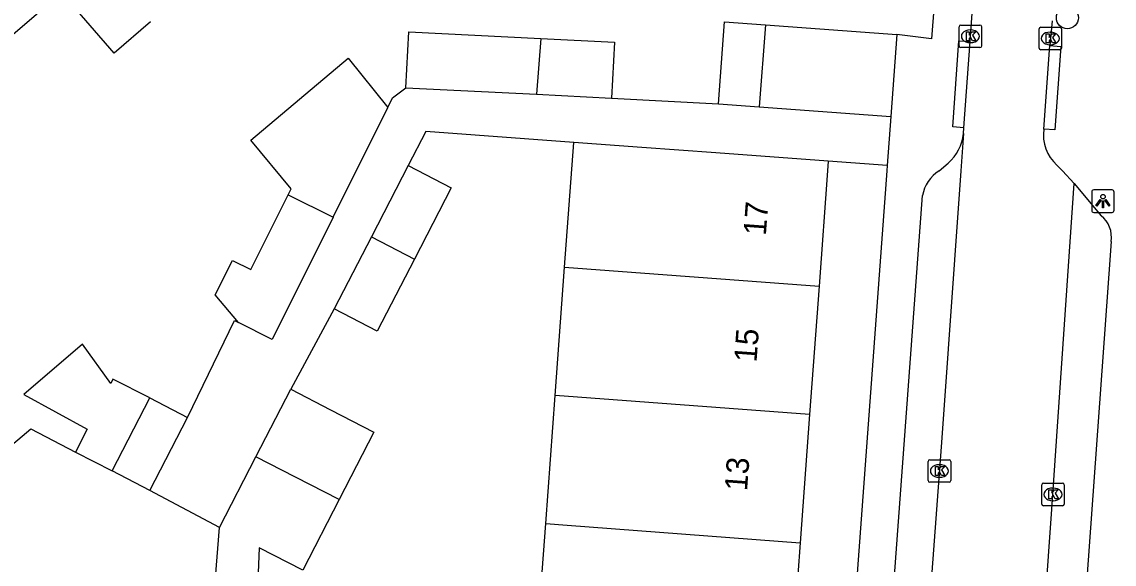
# Model space of a CAD drawing. Extents: x 160304 to 160954, y 383686 to 384161.
# Drawn here: x 160475.81 to 160524.27, y 383982.56 to 384006.62 of the extents above; entities that cross this region are included whole.
import ezdxf

# ---------------------------------------------------------------- set-up
doc = ezdxf.new("R2010")
doc.units = 0
for name, color, linetype in [('IMGEO_Boom', 7, 'Continuous'), ('IMGEO_Kolk', 7, 'Continuous'), ('IMGEO_Lichtpunt', 7, 'Continuous'), ('IMGEO_Muur', 7, 'Continuous'), ('IMGEO_Pand', 7, 'Continuous'), ('IMGEO_Pand_nummerreeks', 7, 'Continuous'), ('IMGEO_Rijbaan_lokaal_open', 7, 'Continuous'), ('IMGEO_Voetpad_open', 7, 'Continuous')]:
    doc.layers.add(name, color=color, linetype=linetype)

msp = doc.modelspace()

# ---------------------------------------------------------------- linework, layer by layer
at = {"layer": 'IMGEO_Boom'}
msp.add_circle((160522.195, 384006.799), 0.489, dxfattribs=at)
at = {"layer": 'IMGEO_Kolk'}
for p, q in [((160517.392, 384005.549), (160517.392, 384006.401)), ((160517.467, 384006.475), (160518.319, 384006.475)), ((160517.88, 384006.255), (160517.905, 384006.255)), ((160518.393, 384006.401), (160518.393, 384005.549)), ((160520.937, 384005.453), (160520.937, 384006.305)), ((160521.012, 384006.379), (160521.864, 384006.379)), ((160521.938, 384006.305), (160521.938, 384005.453)), ((160521.425, 384006.159), (160521.45, 384006.159)), ((160518.319, 384005.475), (160517.467, 384005.475)), ((160517.903, 384005.695), (160517.878, 384005.695)), ((160521.864, 384005.379), (160521.012, 384005.379)), ((160521.448, 384005.599), (160521.423, 384005.599)), ((160516.017, 383986.267), (160516.017, 383987.119)), ((160516.092, 383987.193), (160516.944, 383987.193)), ((160516.505, 383986.973), (160516.53, 383986.973)), ((160517.018, 383987.119), (160517.018, 383986.267)), ((160516.528, 383986.413), (160516.503, 383986.413)), ((160516.944, 383986.193), (160516.092, 383986.193)), ((160521.055, 383985.227), (160521.055, 383986.079)), ((160521.13, 383986.153), (160521.982, 383986.153)), ((160521.543, 383985.933), (160521.568, 383985.933)), ((160522.056, 383986.079), (160522.056, 383985.227)), ((160521.566, 383985.373), (160521.541, 383985.373)), ((160521.982, 383985.153), (160521.13, 383985.153))]:
    msp.add_line(p, q, dxfattribs=at)
for points in [[(160517.392, 384005.549), (160517.392, 384006.401)], [(160517.467, 384006.475), (160518.319, 384006.475)], [(160518.393, 384006.401), (160518.393, 384005.549)], [(160520.937, 384005.453), (160520.937, 384006.305)], [(160521.012, 384006.379), (160521.864, 384006.379)], [(160521.938, 384006.305), (160521.938, 384005.453)], [(160517.713, 384006.175), (160517.836, 384006.175), (160517.836, 384006.024), (160517.966, 384006.175), (160518.13, 384006.175), (160517.984, 384006.024), (160518.137, 384005.775), (160517.985, 384005.775), (160517.9, 384005.939), (160517.836, 384005.872), (160517.836, 384005.775), (160517.713, 384005.775), (160517.713, 384006.175)], [(160521.258, 384006.079), (160521.381, 384006.079), (160521.381, 384005.928), (160521.511, 384006.079), (160521.675, 384006.079), (160521.529, 384005.928), (160521.682, 384005.679), (160521.53, 384005.679), (160521.445, 384005.843), (160521.381, 384005.776), (160521.381, 384005.679), (160521.258, 384005.679), (160521.258, 384006.079)], [(160518.319, 384005.475), (160517.467, 384005.475)], [(160521.864, 384005.379), (160521.012, 384005.379)], [(160516.017, 383986.267), (160516.017, 383987.119)], [(160516.092, 383987.193), (160516.944, 383987.193)], [(160516.338, 383986.893), (160516.461, 383986.893), (160516.461, 383986.742), (160516.591, 383986.893), (160516.755, 383986.893), (160516.609, 383986.742), (160516.762, 383986.493), (160516.61, 383986.493), (160516.525, 383986.657), (160516.461, 383986.59), (160516.461, 383986.493), (160516.338, 383986.493), (160516.338, 383986.893)], [(160517.018, 383987.119), (160517.018, 383986.267)], [(160516.944, 383986.193), (160516.092, 383986.193)], [(160521.055, 383985.227), (160521.055, 383986.079)], [(160521.13, 383986.153), (160521.982, 383986.153)], [(160522.056, 383986.079), (160522.056, 383985.227)], [(160521.376, 383985.853), (160521.499, 383985.853), (160521.499, 383985.702), (160521.629, 383985.853), (160521.793, 383985.853), (160521.647, 383985.702), (160521.8, 383985.453), (160521.648, 383985.453), (160521.563, 383985.617), (160521.499, 383985.55), (160521.499, 383985.453), (160521.376, 383985.453), (160521.376, 383985.853)], [(160521.982, 383985.153), (160521.13, 383985.153)]]:
    msp.add_lwpolyline(points, dxfattribs=at)
for centre, start, end in [((160517.469, 384006.399), 91.552, 178.448), ((160517.469, 384006.399), 91.552, 178.448), ((160518.317, 384006.399), 1.552, 88.448), ((160518.317, 384006.399), 1.552, 88.448), ((160521.014, 384006.303), 91.552, 178.448), ((160521.014, 384006.303), 91.552, 178.448), ((160521.862, 384006.303), 1.552, 88.448), ((160521.862, 384006.303), 1.552, 88.448), ((160517.469, 384005.551), 181.552, 268.448), ((160517.469, 384005.551), 181.552, 268.448), ((160518.317, 384005.551), 271.552, 358.448), ((160518.317, 384005.551), 271.552, 358.448), ((160521.014, 384005.455), 181.552, 268.448), ((160521.014, 384005.455), 181.552, 268.448), ((160521.862, 384005.455), 271.552, 358.448), ((160521.862, 384005.455), 271.552, 358.448), ((160516.094, 383987.117), 91.552, 178.448), ((160516.094, 383987.117), 91.552, 178.448), ((160516.942, 383987.117), 1.552, 88.448), ((160516.942, 383987.117), 1.552, 88.448), ((160516.094, 383986.269), 181.552, 268.448), ((160516.094, 383986.269), 181.552, 268.448), ((160516.942, 383986.269), 271.552, 358.448), ((160516.942, 383986.269), 271.552, 358.448), ((160521.132, 383986.077), 91.552, 178.448), ((160521.132, 383986.077), 91.552, 178.448), ((160521.98, 383986.077), 1.552, 88.448), ((160521.98, 383986.077), 1.552, 88.448), ((160521.132, 383985.229), 181.552, 268.448), ((160521.132, 383985.229), 181.552, 268.448), ((160521.98, 383985.229), 271.552, 358.448), ((160521.98, 383985.229), 271.552, 358.448)]:
    msp.add_arc(centre, 0.0765, start, end, dxfattribs=at)
for centre, major_axis, ratio, start_param, end_param in [((160517.879, 384005.975), (-0.387, 0.002), 0.722429, 4.712389, 7.853982), ((160517.904, 384005.975), (-0.39, 0.002), 0.717154, 1.570796, 4.712389), ((160521.424, 384005.879), (-0.387, 0.002), 0.722429, 4.712389, 7.853982), ((160521.449, 384005.879), (-0.39, 0.002), 0.717154, 1.570796, 4.712389), ((160516.504, 383986.693), (-0.387, 0.002), 0.722429, 4.712389, 7.853982), ((160516.529, 383986.693), (-0.39, 0.002), 0.717154, 1.570796, 4.712389), ((160521.542, 383985.653), (-0.387, 0.002), 0.722429, 4.712389, 7.853982), ((160521.567, 383985.653), (-0.39, 0.002), 0.717154, 1.570796, 4.712389)]:
    msp.add_ellipse(centre, major_axis=major_axis, ratio=ratio, start_param=start_param, end_param=end_param, dxfattribs=at)
at = {"layer": 'IMGEO_Lichtpunt'}
for p, q in [((160523.274, 383999.065), (160523.274, 383998.258)), ((160523.274, 383999.065), (160523.274, 383998.258)), ((160524.176, 383999.16), (160523.368, 383999.16)), ((160524.176, 383999.16), (160523.368, 383999.16)), ((160524.27, 383998.258), (160524.27, 383999.065)), ((160524.27, 383998.258), (160524.27, 383999.065)), ((160523.368, 383998.164), (160524.176, 383998.164)), ((160523.368, 383998.164), (160524.176, 383998.164))]:
    msp.add_line(p, q, dxfattribs=at)
for points in [[(160523.648, 383998.729), (160523.687, 383998.701), (160523.499, 383998.439), (160523.461, 383998.466), (160523.648, 383998.729)], [(160523.75, 383998.681), (160523.797, 383998.681), (160523.797, 383998.359), (160523.75, 383998.359), (160523.75, 383998.681)], [(160523.86, 383998.701), (160523.898, 383998.728), (160524.085, 383998.466), (160524.046, 383998.438), (160523.86, 383998.701)]]:
    msp.add_lwpolyline(points, dxfattribs=at)
msp.add_circle((160523.773, 383998.863), 0.0994, dxfattribs=at)
for centre, start, end in [((160523.368, 383999.065), 90, 180), ((160523.368, 383999.065), 90, 180), ((160524.176, 383999.065), 0, 90), ((160524.176, 383999.065), 0, 90), ((160523.368, 383998.258), 180, 270), ((160523.368, 383998.258), 180, 270), ((160524.176, 383998.258), 270, 0), ((160524.176, 383998.258), 270, 360)]:
    msp.add_arc(centre, 0.0946, start, end, dxfattribs=at)
at = {"layer": 'IMGEO_Muur'}
msp.add_lwpolyline([(160516.865, 384014.823), (160516.165, 384005.868), (160514.632, 384006.049)], dxfattribs=at)
at = {"layer": 'IMGEO_Pand'}
for points in [[(160481.518, 384006.62), (160479.908, 384005.23), (160477.59, 384007.917), (160474.915, 384005.61)], [(160506.718, 384002.979), (160506.985, 384006.611), (160508.803, 384006.477)], [(160508.803, 384006.477), (160508.529, 384002.846)], [(160508.803, 384006.477), (160514.632, 384006.049)], [(160492.852, 384003.691), (160492.976, 384006.17), (160498.838, 384005.876)], [(160498.838, 384005.876), (160498.645, 384003.401)], [(160498.838, 384005.876), (160502.101, 384005.712), (160501.977, 384003.234)], [(160514.632, 384006.049), (160514.365, 384002.417)], [(160487.627, 383998.942), (160487.762, 383999.213), (160485.973, 384001.37), (160490.297, 384005.007), (160492.045, 384002.818)], [(160492.852, 384003.691), (160498.645, 384003.401)], [(160498.645, 384003.401), (160501.977, 384003.234)], [(160489.621, 383997.952), (160492.045, 384002.818)], [(160506.718, 384002.979), (160508.529, 384002.846)], [(160508.529, 384002.846), (160514.365, 384002.417)], [(160499.893, 383995.737), (160500.3, 384001.271)], [(160511.589, 384000.441), (160506.603, 384000.808), (160503.321, 384001.049), (160500.3, 384001.271)], [(160511.589, 384000.441), (160511.557, 384000), (160511.181, 383994.892)], [(160492.955, 384000.238), (160491.321, 383997.083)], [(160492.955, 384000.238), (160494.862, 383999.249), (160493.227, 383996.093)], [(160485.419, 383993.28), (160484.396, 383994.509), (160485.154, 383996.031), (160485.973, 383995.623), (160487.627, 383998.942)], [(160487.627, 383998.942), (160489.621, 383997.952)], [(160489.621, 383997.952), (160486.92, 383992.532), (160485.419, 383993.28)], [(160491.321, 383997.083), (160489.665, 383993.887)], [(160491.321, 383997.083), (160493.227, 383996.093)], [(160493.227, 383996.093), (160491.573, 383992.899), (160489.665, 383993.887)], [(160499.474, 383990.044), (160499.893, 383995.737)], [(160499.893, 383995.737), (160511.181, 383994.892)], [(160511.181, 383994.892), (160510.762, 383989.202)], [(160481.488, 383989.933), (160479.858, 383990.773), (160479.755, 383990.573), (160478.498, 383992.32), (160475.906, 383990.092), (160478.71, 383988.547), (160478.188, 383987.535)], [(160486.199, 383987.321), (160487.744, 383990.315)], [(160487.744, 383990.315), (160489.5, 383989.409), (160491.435, 383988.411), (160489.893, 383985.421)], [(160479.821, 383986.693), (160481.488, 383989.933)], [(160481.488, 383989.933), (160483.16, 383989.07)], [(160499.056, 383984.364), (160499.474, 383990.044)], [(160510.762, 383989.202), (160499.474, 383990.044)], [(160481.491, 383985.832), (160483.16, 383989.07)], [(160510.762, 383989.202), (160510.343, 383983.504)], [(160478.188, 383987.535), (160479.821, 383986.693)], [(160484.585, 383984.191), (160486.199, 383987.321)], [(160489.893, 383985.421), (160487.957, 383986.417), (160486.199, 383987.321)], [(160481.491, 383985.832), (160479.821, 383986.693)], [(160489.893, 383985.421), (160488.278, 383982.289), (160486.342, 383983.285), (160486.198, 383979.584)], [(160484.225, 383979.728), (160484.585, 383984.191)], [(160501.658, 383978.45), (160500, 383978.572), (160498.637, 383978.673), (160499.056, 383984.364)], [(160499.056, 383984.364), (160500, 383984.292), (160510.343, 383983.504)], [(160510.343, 383983.504), (160509.925, 383977.831)]]:
    msp.add_lwpolyline(points, dxfattribs=at)
at = {"layer": 'IMGEO_Rijbaan_lokaal_open'}
for points in [[(160517.877, 384005.739), (160519.366, 384026.716)], [(160521.524, 384006.661), (160521.414, 384005.562)], [(160517.605, 384001.92), (160517.877, 384005.739)], [(160521.148, 384001.857), (160521.414, 384005.562)], [(160517.587, 384001.661), (160517.605, 384001.92)], [(160517.587, 384001.661), (160517.469, 384000), (160516.629, 383988.167), (160515.815, 383977.238)], [(160521.734, 384000.26), (160521.979, 384000), (160522.497, 383999.449)], [(160520.923, 383976.868), (160521.51, 383984.995), (160522.497, 383999.449)], [(160473.521, 383986.297), (160476.215, 383988.562), (160478.188, 383987.535)], [(160484.585, 383984.191), (160481.491, 383985.832)]]:
    msp.add_lwpolyline(points, dxfattribs=at)
msp.add_arc((160522.903, 384001.595), 1.774, 171.5028, 228.7972, dxfattribs=at)
at = {"layer": 'IMGEO_Voetpad_open'}
for points in [[(160516.865, 384014.823), (160516.165, 384005.868), (160514.632, 384006.049)], [(160517.605, 384001.92), (160517.108, 384001.957), (160517.379, 384005.776), (160517.877, 384005.739)], [(160521.414, 384005.562), (160521.912, 384005.525), (160521.646, 384001.82), (160521.148, 384001.857)], [(160492.045, 384002.818), (160492.261, 384003.252), (160492.852, 384003.691)], [(160501.977, 384003.234), (160506.718, 384002.979)], [(160514.365, 384002.417), (160514.205, 384000.248)], [(160500.3, 384001.271), (160493.74, 384001.753), (160492.955, 384000.238)], [(160514.205, 384000.248), (160511.589, 384000.441)], [(160514.205, 384000.248), (160514.187, 384000), (160510.426, 383949.047)], [(160516.507, 384000), (160516.903, 384000.346)], [(160522.497, 383999.449), (160523.692, 383998.016)], [(160512.225, 383950.713), (160515.771, 383998.911)], [(160524.135, 383996.873), (160520.769, 383950.16)], [(160489.665, 383993.887), (160487.744, 383990.315)], [(160483.16, 383989.07), (160485.244, 383993.366), (160485.419, 383993.28)]]:
    msp.add_lwpolyline(points, dxfattribs=at)
for centre, radius, start, end in [((160515.592, 384001.863), 2.005, 310.8247, 354.2127), ((160517.317, 383998.659), 1.567, 121.1463, 170.7482), ((160522.942, 383997.068), 1.209, 350.7282, 51.6421)]:
    msp.add_arc(centre, radius, start, end, dxfattribs=at)

# ---------------------------------------------------------------- texts
at = {"layer": 'IMGEO_Pand_nummerreeks'}
for s, rotation, p in [('17', 85.7947, (160508.819, 383997.118)), ('15', 85.789, (160508.404, 383991.491)), ('13', 85.789, (160507.984, 383985.784))]:
    msp.add_text(s, height=1, rotation=rotation, dxfattribs=at).set_placement(p)

doc.saveas('drawing.dxf')
